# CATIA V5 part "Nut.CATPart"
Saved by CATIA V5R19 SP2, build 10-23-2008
Part number: Nut
Definition: Nut
Nomenclature: Nut
Source: Unknown
Bounding box of the stored display mesh (mm): x -14.318 to 14.318, y -12.4 to 12.4, z 1.5 to 4.4
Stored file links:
  Z:\fausse table rondelle-20220905T211342Z-001\fausse table rondelle\Nut.CATPart
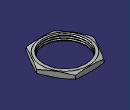
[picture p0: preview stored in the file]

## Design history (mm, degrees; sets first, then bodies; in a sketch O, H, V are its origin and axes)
AxisSystem1: origin (0, 0, 0), X (1, 0, 0), Y (0, 1, 0), Z (0, 0, 1)
Body1 "Nut" (main body)
  Solid1: solid without history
